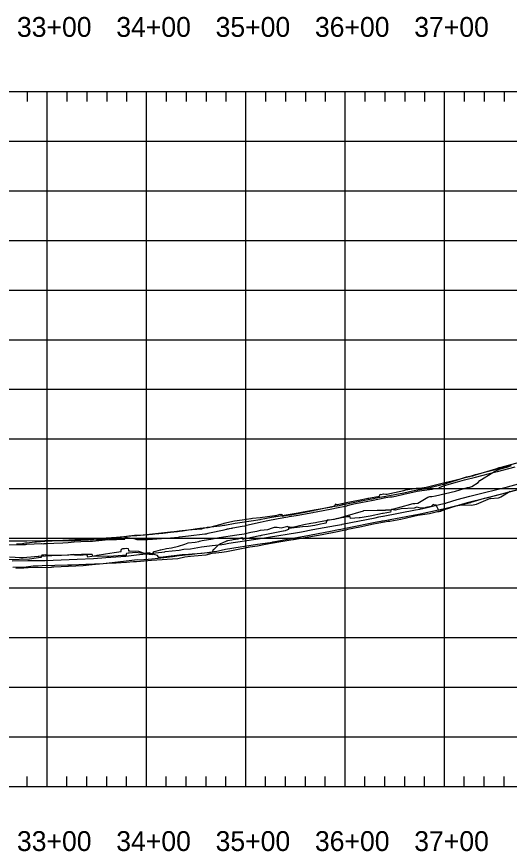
# Model space of a CAD drawing. Extents: x 704797 to 712284, y 374940 to 376945.
# Drawn here: x 710403 to 710899, y 375160 to 376001 of the extents above; entities that cross this region are included whole.
import ezdxf

# ---------------------------------------------------------------- set-up
doc = ezdxf.new("R2010")
doc.units = 0
for name, color, linetype in [('10', 7, 'Continuous'), ('12', 7, 'Continuous'), ('13', 7, 'Continuous'), ('61', 7, 'Continuous'), ('63', 7, 'Continuous'), ('Existing', 7, 'Continuous')]:
    doc.layers.add(name, color=color, linetype=linetype)

msp = doc.modelspace()

# ---------------------------------------------------------------- linework, layer by layer
at = {"layer": '10'}
for points in [[(710395.99, 375456.88), (710407.07, 375456.25), (710408.48, 375456.14), (710409.57, 375455.96), (710424.75, 375457.33), (710425, 375457.33), (710425.08, 375457.36), (710425.42, 375457.38), (710445.23, 375458.38), (710448.16, 375458.54), (710455.68, 375458.92), (710459.05, 375459), (710461.28, 375458.86), (710463.87, 375458.68), (710467.27, 375458.55), (710469.98, 375458.86), (710472.64, 375459.07), (710473.73, 375458.91), (710474.02, 375457.75), (710474.27, 375456.75), (710482.96, 375458.25), (710483.96, 375458.42), (710492.64, 375459.78), (710501.1, 375461.14), (710508.11, 375462.3), (710508.28, 375463.51), (710508.45, 375464.39), (710510, 375465.13), (710511.76, 375465.31), (710514.11, 375465.47), (710515.23, 375465.25), (710515.5, 375463.11), (710515.53, 375462.85), (710516.87, 375462.72), (710525.67, 375462.59), (710533.53, 375459.93), (710536.48, 375459.44), (710540.28, 375459.05), (710540.43, 375459.85), (710540.9, 375461.81), (710541.35, 375462.08), (710545.54, 375463.11), (710547.73, 375463.7), (710548.21, 375463.83), (710553.89, 375465.1), (710558.93, 375465.98), (710565.95, 375467.56), (710572.37, 375469.51), (710575.62, 375470.99), (710582.67, 375471.53), (710586.45, 375472.27), (710587.05, 375472.4), (710589.74, 375473.16), (710596.16, 375474.34), (710598.59, 375474.61), (710607.02, 375476.25), (710624.66, 375478.94), (710631.93, 375480.02), (710638.94, 375481.67), (710644.68, 375482.77), (710646.18, 375483.07), (710648.69, 375483.74), (710655.75, 375484.4), (710660.72, 375485.87), (710662.59, 375486.75), (710664.32, 375486.81), (710665.22, 375486.67), (710669.47, 375486.08), (710676.17, 375487.6), (710676.73, 375485.92), (710676.88, 375485.39), (710676.98, 375485.47), (710688.26, 375487.1), (710690.8, 375487.3), (710696.41, 375487.53), (710703.24, 375488.62), (710704.42, 375488.9), (710706.2, 375489.3), (710709.04, 375489.93), (710712.5, 375490.55), (710714.67, 375491.12), (710714.95, 375491.18), (710715.01, 375491.53), (710715.52, 375493.97), (710716.61, 375494.08), (710723.03, 375494.86), (710724.95, 375495.35), (710729.31, 375496.5), (710733.86, 375497.66), (710752.06, 375503.16), (710752.48, 375503.29), (710766.11, 375503.62), (710774.35, 375503.62), (710774.58, 375504.06), (710779.14, 375503.97), (710793.86, 375508), (710796.21, 375508.8), (710802.15, 375510.45), (710803.83, 375510.38), (710807.03, 375510.94), (710816.92, 375516.71), (710818.97, 375517.49), (710821.03, 375517.65), (710824.86, 375518.17), (710844.76, 375522.84), (710853.49, 375525.66), (710856.77, 375526.51), (710859.21, 375527.08), (710861.34, 375527.64), (710867.61, 375531.53), (710869.49, 375533.69), (710870.89, 375534.57), (710880.71, 375540.62), (710885.06, 375543.22), (710890.29, 375545.3), (710896.37, 375547.23), (710901.24, 375548.79)], [(710899.81, 375522.54), (710890.51, 375516.7), (710887.84, 375515.87), (710880, 375515.19), (710879.64, 375515.6), (710865.5, 375509.33), (710861.45, 375508.5), (710861.29, 375508.6), (710851.59, 375508.76), (710844.84, 375507.89), (710844.3, 375507.52), (710835.99, 375505.06), (710829.94, 375503.8), (710828.06, 375503.45), (710825.4, 375508.81), (710824.78, 375508.87), (710823.68, 375508.82), (710822.26, 375509.37), (710820.41, 375507.38), (710814.99, 375506.29), (710814.37, 375506.2), (710809.59, 375505.75), (710806.04, 375506.63), (710803.08, 375505.66), (710790.27, 375505.04), (710784.3, 375503.8), (710783.81, 375503.7), (710780.4, 375504.41), (710780.08, 375504.47), (710780.07, 375504.44), (710779.53, 375501.77), (710779.46, 375501.76), (710772, 375500.45), (710771.26, 375500.32), (710758.9, 375497.6), (710748.78, 375496), (710747.72, 375495.88), (710743.57, 375495.66), (710739.14, 375495.3), (710738.64, 375496.8), (710738.47, 375497.3), (710738.23, 375497.23), (710737.16, 375496.99), (710736.54, 375496.92), (710733.73, 375496.58), (710732.36, 375496.41), (710730.13, 375496), (710727.31, 375495.54), (710723.98, 375494.79), (710712.29, 375492.59), (710705.28, 375491.36), (710703.8, 375491.11), (710699.19, 375490.35), (710692.23, 375489.04), (710680.65, 375486.42), (710678.86, 375486.41), (710677.89, 375486.74), (710677.65, 375486.82), (710676.8, 375484.62), (710676.71, 375484.3), (710673.98, 375483.33), (710673.29, 375483.06), (710671.83, 375482.66), (710671.47, 375482.57), (710654.68, 375479.17), (710649.29, 375478.24), (710648.41, 375478.03), (710647.86, 375477.86), (710633.39, 375474.96), (710631.35, 375474.4), (710630.83, 375474.3), (710630.62, 375475.74), (710630.09, 375475.73), (710629.51, 375475.87), (710625.78, 375474.67), (710625.37, 375474.63), (710624.87, 375474.48), (710623.29, 375474.17), (710620.91, 375473.92), (710619.59, 375473.54), (710615.18, 375472.85), (710614.62, 375472.67), (710614.1, 375472.45), (710613.52, 375472.15), (710608.41, 375470.02), (710607.21, 375469.25), (710606.05, 375468.4), (710605.62, 375468.03), (710603.95, 375466.5), (710601.41, 375464.19), (710600.56, 375463.33), (710600.52, 375463.29), (710600.49, 375463.2), (710599.78, 375461.41), (710598.53, 375461.11), (710597.03, 375460.8), (710595.96, 375460.63), (710584.84, 375459.84), (710577.27, 375458.9), (710569.78, 375458.69), (710550.38, 375456.42), (710548.43, 375456.22), (710546.95, 375456.11), (710546.1, 375456.14), (710545.94, 375456.47), (710544.89, 375458.13), (710539.97, 375459.5), (710539.65, 375459.6), (710536.51, 375460.7), (710530.55, 375460.14), (710522.95, 375461.16), (710516.32, 375460.39), (710515.17, 375460.35), (710513.77, 375460.24), (710513.43, 375459.4), (710513.2, 375458.53), (710513.13, 375458.25), (710512.76, 375458.24), (710509.71, 375458.16), (710496.33, 375457.18), (710496.22, 375457.17), (710495.8, 375457.17), (710494.36, 375457.16), (710479.87, 375457.58), (710479.81, 375457.57), (710479.71, 375457.91), (710479.21, 375459.24), (710476.15, 375459.11), (710475.18, 375459.16), (710474.47, 375459.2), (710468.39, 375459.12), (710460.14, 375458.92), (710459.88, 375458.98), (710454.31, 375458.54), (710446, 375458.13), (710444.23, 375458.08), (710439.25, 375458.24), (710433.13, 375458.59), (710431.69, 375458.62), (710430.49, 375458.54), (710429.46, 375458.44), (710428.22, 375458.34), (710427.87, 375456.71), (710427.72, 375456.02), (710425.18, 375455.83), (710416.03, 375454.42), (710405.48, 375454.11), (710393.53, 375453.9)]]:
    msp.add_lwpolyline(points, dxfattribs=at)
at = {"layer": '12'}
for points in [[(710398.39, 375452.87), (710414.32, 375453.15), (710424.26, 375453.21), (710431.78, 375453.08), (710447.71, 375453.63), (710464.04, 375454.34), (710480.28, 375455), (710492.66, 375456.04), (710512.89, 375457.56), (710523.67, 375458.81), (710552.14, 375461.95), (710552.45, 375461.98), (710566.76, 375463.49), (710571.2, 375464.34), (710577.92, 375464.94), (710589.09, 375466.72), (710599.91, 375468.2), (710609.76, 375469.13), (710611.91, 375469.45), (710616.6, 375470.37), (710650.7, 375475.42), (710652.7, 375475.77), (710656.46, 375476.47), (710685.67, 375481.36), (710685.83, 375481.38), (710689.76, 375482.08), (710701.21, 375484.13), (710724.08, 375488.24), (710728.13, 375489.02), (710730.14, 375489.43), (710730.26, 375489.49), (710730.77, 375489.66), (710763.88, 375496.16), (710767.71, 375496.94), (710771.7, 375497.73), (710772.13, 375497.71), (710804.48, 375503.94), (710808.82, 375504.91), (710811.85, 375505.35), (710834.36, 375510.7), (710834.68, 375510.72), (710834.98, 375510.77), (710835.69, 375511.11), (710846.59, 375514.59), (710859.19, 375517.78), (710860.69, 375518.16), (710861.91, 375518.48), (710897.08, 375527.35), (710908.36, 375530.43)], [(710399.3, 375446.46), (710412.7, 375446.66), (710414.93, 375447.06), (710419.55, 375447.54), (710424.85, 375447.68), (710428.62, 375447.9), (710454.23, 375448.78), (710456.62, 375448.83), (710456.95, 375448.82), (710457.25, 375448.81), (710457.52, 375448.79), (710457.77, 375448.78), (710458, 375448.78), (710458.41, 375448.78), (710472.79, 375449.34), (710490.21, 375450), (710493.11, 375450.34), (710504.96, 375451.81), (710519.13, 375453.43), (710524.2, 375453.98), (710526.58, 375453.84), (710535.58, 375454.58), (710542.35, 375455.22), (710559.91, 375457.18), (710568.98, 375458.29), (710569.53, 375458.41), (710570.14, 375458.52), (710570.85, 375458.62), (710571.66, 375458.73), (710572.59, 375458.85), (710576.09, 375459.29), (710579.57, 375459.71), (710589.31, 375460.47), (710599.86, 375461.91), (710601.6, 375462.08), (710603.18, 375462.28), (710613.36, 375464.59), (710627.92, 375466.96), (710645.34, 375469.69), (710658.16, 375471.06), (710659.3, 375471.19), (710660.42, 375471.45), (710660.94, 375471.8), (710661.12, 375471.96), (710679.51, 375475.13), (710692.55, 375477.59), (710718.91, 375482.47), (710727.13, 375484.2), (710727.73, 375484.28), (710735.9, 375485.98), (710765.66, 375491.93), (710769.65, 375492.64), (710770.08, 375492.7), (710770.9, 375492.86), (710772.11, 375493.09), (710802.36, 375498.88), (710809.32, 375500), (710827.62, 375504), (710836.75, 375506), (710843.45, 375507.63), (710860.33, 375511.62), (710860.46, 375511.8), (710874.16, 375515.74), (710893.69, 375520.74), (710915.47, 375526.74)]]:
    msp.add_lwpolyline(points, dxfattribs=at)
at = {"layer": '13'}
msp.add_lwpolyline([(710913.53, 375525.73), (710892.38, 375520.16), (710875.62, 375515.81), (710856.57, 375511.01), (710845.34, 375507.82), (710833.51, 375504.05), (710829.91, 375502.33), (710828.36, 375502.04), (710826.76, 375501.96), (710818.77, 375500.06), (710806.94, 375498.35), (710789.86, 375494.53), (710778.69, 375492.38), (710778.22, 375492.4), (710777.1, 375492.44), (710762.37, 375489.54), (710748.54, 375486.76), (710736.28, 375484.38), (710734.3, 375483.72), (710733.84, 375483.52), (710726.07, 375481.93), (710710.78, 375479.06), (710697.34, 375476.67), (710681.77, 375473.95), (710681.17, 375473.88), (710669.08, 375471.88), (710653.66, 375469.02), (710645.59, 375467.64), (710637.88, 375466.51), (710614.24, 375461.95), (710609.74, 375461.28), (710603.63, 375460.36), (710599.6, 375459.97), (710593.44, 375458.36), (710578.12, 375457.17), (710572.43, 375456.48), (710565.29, 375454.85), (710538.67, 375453.13), (710527.76, 375451.96), (710523.85, 375451.82), (710520.64, 375451.67), (710513.74, 375451.08), (710503.08, 375450.3), (710494.32, 375450.11), (710482.34, 375448.97), (710479.11, 375448.63), (710478.8, 375448.65), (710469.92, 375447.83), (710469.84, 375447.82), (710440.42, 375446.32), (710438.61, 375446.21), (710437.63, 375446.16), (710437.37, 375446.18), (710414.5, 375445.57), (710410.29, 375445.46), (710407.23, 375445.28), (710402.16, 375445.16)], dxfattribs=at)
at = {"layer": '61'}
for p, q in [((708133.69, 375925.47), (712133.69, 375925.47)), ((710413.69, 375925.47), (710413.69, 375915.47)), ((710433.69, 375225.47), (710433.69, 375925.47)), ((710453.69, 375925.47), (710453.69, 375915.47)), ((710473.69, 375925.47), (710473.69, 375915.47)), ((710493.69, 375925.47), (710493.69, 375915.47)), ((710513.69, 375925.47), (710513.69, 375915.47)), ((710533.69, 375225.47), (710533.69, 375925.47)), ((710553.69, 375925.47), (710553.69, 375915.47)), ((710573.69, 375925.47), (710573.69, 375915.47)), ((710593.69, 375925.47), (710593.69, 375915.47)), ((710613.69, 375925.47), (710613.69, 375915.47)), ((710633.69, 375225.47), (710633.69, 375925.47)), ((710653.69, 375925.47), (710653.69, 375915.47)), ((710673.69, 375925.47), (710673.69, 375915.47)), ((710693.69, 375925.47), (710693.69, 375915.47)), ((710713.69, 375925.47), (710713.69, 375915.47)), ((710733.69, 375225.47), (710733.69, 375925.47)), ((710753.69, 375925.47), (710753.69, 375915.47)), ((710773.69, 375925.47), (710773.69, 375915.47)), ((710793.69, 375925.47), (710793.69, 375915.47)), ((710813.69, 375925.47), (710813.69, 375915.47)), ((710833.69, 375225.47), (710833.69, 375925.47)), ((710853.69, 375925.47), (710853.69, 375915.47)), ((710873.69, 375925.47), (710873.69, 375915.47)), ((710893.69, 375925.47), (710893.69, 375915.47)), ((708133.69, 375875.47), (712133.69, 375875.47)), ((708133.69, 375825.47), (712133.69, 375825.47)), ((708133.69, 375775.47), (712133.69, 375775.47)), ((708133.69, 375725.47), (712133.69, 375725.47)), ((708133.69, 375675.47), (712133.69, 375675.47)), ((708133.69, 375625.47), (712133.69, 375625.47)), ((708133.69, 375575.47), (712133.69, 375575.47)), ((708133.69, 375525.47), (712133.69, 375525.47)), ((708133.69, 375475.47), (712133.69, 375475.47)), ((708133.69, 375425.47), (712133.69, 375425.47)), ((708133.69, 375375.47), (712133.69, 375375.47)), ((708133.69, 375325.47), (712133.69, 375325.47)), ((708133.69, 375275.47), (712133.69, 375275.47)), ((710413.69, 375225.47), (710413.69, 375235.47)), ((710453.69, 375225.47), (710453.69, 375235.47)), ((710473.69, 375225.47), (710473.69, 375235.47)), ((710493.69, 375225.47), (710493.69, 375235.47)), ((710513.69, 375225.47), (710513.69, 375235.47)), ((710553.69, 375225.47), (710553.69, 375235.47)), ((710573.69, 375225.47), (710573.69, 375235.47)), ((710593.69, 375225.47), (710593.69, 375235.47)), ((710613.69, 375225.47), (710613.69, 375235.47)), ((710653.69, 375225.47), (710653.69, 375235.47)), ((710673.69, 375225.47), (710673.69, 375235.47)), ((710693.69, 375225.47), (710693.69, 375235.47)), ((710713.69, 375225.47), (710713.69, 375235.47)), ((710753.69, 375225.47), (710753.69, 375235.47)), ((710773.69, 375225.47), (710773.69, 375235.47)), ((710793.69, 375225.47), (710793.69, 375235.47)), ((710813.69, 375225.47), (710813.69, 375235.47)), ((710853.69, 375225.47), (710853.69, 375235.47)), ((710873.69, 375225.47), (710873.69, 375235.47)), ((710893.69, 375225.47), (710893.69, 375235.47)), ((708133.69, 375225.47), (712133.69, 375225.47))]:
    msp.add_line(p, q, dxfattribs=at)
at = {"layer": '63'}
for points in [[(710402.77, 375469.93), (710407.34, 375470.02), (710411.98, 375470.88), (710413.33, 375471.02), (710421.36, 375471.87), (710422.96, 375471.92), (710431.4, 375472.42), (710438.76, 375472.85), (710446.17, 375473.12), (710449.47, 375473.19), (710455.02, 375473.3), (710456.21, 375473.29), (710457.27, 375473.24), (710458.22, 375473.18), (710459.06, 375473.15), (710459.87, 375473.16), (710461.29, 375473.17), (710467.54, 375473.44), (710483.44, 375474.12), (710485.6, 375474.29), (710490.63, 375474.7), (710494.69, 375475.18), (710503.67, 375476.32), (710513.65, 375477.59), (710516.12, 375477.94), (710521.74, 375478.56), (710523.53, 375478.75), (710527.76, 375478.51), (710539.81, 375479.57), (710542.15, 375479.77), (710550.13, 375480.58), (710557.87, 375481.47), (710564.9, 375482.28), (710565.91, 375482.49), (710567.06, 375482.69), (710568.41, 375482.89), (710570.01, 375483.09), (710571.87, 375483.32), (710575.94, 375483.81), (710579.33, 375484.22), (710579.7, 375484.26), (710589.31, 375484.96), (710591.27, 375485.63), (710594.01, 375486.33), (710594.27, 375486.4), (710595.91, 375486.33), (710597.46, 375486.63), (710598.98, 375487.07), (710611.4, 375490.5), (710612.07, 375490.68), (710614.51, 375491.31), (710622.41, 375492.87), (710630.14, 375494.04), (710638.87, 375495.37), (710639.08, 375495.42), (710640.45, 375495.55), (710648.21, 375496.47), (710662.96, 375498.24), (710664.04, 375498.49), (710666.28, 375499.14), (710668.25, 375499.71), (710668.49, 375499.34), (710669.4, 375499.58), (710669.68, 375499.54), (710669.88, 375499.58), (710669.9, 375499.53), (710670.46, 375497.55), (710670.82, 375497.87), (710673.72, 375498.27), (710684.34, 375500.24), (710699.71, 375503.08), (710701, 375503.32), (710701.17, 375503.36), (710701.66, 375503.48), (710702.06, 375503.57), (710702.41, 375503.65), (710702.63, 375503.7), (710704.74, 375504.16), (710720.48, 375507.5), (710722.44, 375507.91), (710722.83, 375507.97), (710723.33, 375508.03), (710724.02, 375509.54), (710724.19, 375509.93), (710724.65, 375510), (710725.12, 375509.61), (710726.06, 375509.55), (710736.31, 375511.75), (710738.55, 375512.19), (710750.42, 375514.49), (710756.61, 375515.73), (710757.58, 375515.93), (710759.24, 375516.28), (710768.18, 375517.88), (710768.4, 375518.08), (710768.45, 375518.1), (710768.95, 375519.71), (710769.15, 375519.96), (710769.99, 375519.53), (710772.25, 375520.05), (710774.68, 375520), (710776.06, 375519.97), (710778.65, 375520.67), (710792.75, 375523.68), (710795.01, 375524.16), (710805.29, 375525.89), (710808.06, 375525.77), (710810.82, 375526.25), (710815.21, 375527.02), (710819.41, 375527.91), (710828.88, 375530.36), (710834.02, 375531.68), (710841.4, 375533.43), (710846.95, 375534.75), (710858.72, 375537.55), (710859.69, 375537.82), (710860.01, 375537.99), (710862.15, 375538.5), (710865.02, 375539.34), (710885.34, 375545.26), (710888.7, 375546.63), (710889.2, 375546.79), (710890.74, 375547.15), (710924.02, 375556.13)], [(710395.27, 375468.69), (710406.5, 375469.02), (710409.17, 375469.07), (710409.68, 375469.09), (710410.25, 375469.17), (710411.98, 375469.31), (710413.33, 375469.38), (710428.03, 375470.13), (710428.37, 375470.04), (710430.48, 375469.92), (710430.49, 375470.33), (710431.4, 375470.33), (710431.68, 375470.33), (710433.92, 375470.1), (710440.52, 375470.43), (710449.47, 375470.9), (710454.85, 375471.19), (710460.93, 375471.87), (710467.54, 375472.13), (710476.9, 375472.6), (710477.84, 375472.58), (710477.88, 375472.55), (710479.26, 375472.49), (710485.6, 375473.12), (710495.39, 375474.1), (710495.49, 375474.11), (710499.96, 375474.19), (710503.67, 375474.3), (710511.81, 375474.56), (710511.88, 375474.55), (710511.97, 375474.56), (710512.02, 375476.26), (710514.66, 375476.07), (710521.09, 375475.3), (710521.74, 375475.1), (710523.15, 375474.69), (710523.92, 375474.35), (710525.47, 375474.3), (710526.27, 375474.22), (710534.61, 375474.15), (710539.81, 375474.58), (710557.87, 375476.03), (710565.67, 375476.65), (710566.34, 375476.68), (710566.48, 375476.69), (710566.5, 375476.7), (710566.96, 375476.76), (710575.94, 375477.83), (710592.65, 375479.81), (710594.01, 375480.04), (710594.97, 375480.2), (710595.89, 375480.46), (710597.17, 375480.8), (710612.07, 375484.09), (710614.13, 375484.54), (710614.6, 375484.69), (710615.29, 375484.88), (710616.23, 375485.1), (710617.43, 375485.36), (710618.98, 375485.67), (710619.85, 375485.77), (710620.71, 375485.93), (710630.14, 375487.65), (710632.69, 375488.11), (710633.99, 375488.44), (710634.46, 375488.61), (710648.21, 375491.77), (710651.25, 375492.46), (710654.23, 375492.98), (710666.28, 375495.26), (710676.04, 375497.1), (710678.76, 375497.56), (710679.6, 375497.66), (710684.34, 375498.5), (710701.11, 375501.47), (710702.41, 375501.7), (710704.49, 375502.08), (710720.48, 375505.12), (710725.16, 375506.01), (710735.43, 375508.13), (710736.02, 375508.4), (710738.55, 375509.24), (710738.61, 375509.27), (710742.39, 375510), (710756.61, 375512.88), (710760.34, 375513.64), (710774.68, 375516.47), (710779.04, 375517.33), (710781.03, 375517.26), (710784.58, 375517.94), (710792.75, 375519.76), (710806.24, 375522.77), (710810.82, 375523.42), (710821.43, 375524.95), (710823.81, 375525.51), (710825.9, 375525.61), (710827.93, 375525.99), (710828.88, 375526.44), (710832.65, 375528.24), (710835.98, 375529.29), (710846.95, 375532.4), (710853.88, 375534.35), (710865.02, 375537.13), (710885.49, 375542.23), (710886.99, 375542.62), (710905.05, 375547.33)]]:
    msp.add_lwpolyline(points, dxfattribs=at)
at = {"layer": 'Existing'}
msp.add_lwpolyline([(710395.27, 375472.86), (710404.92, 375472.97), (710405.53, 375472.97), (710413.33, 375473), (710431.4, 375473.08), (710436.93, 375473.1), (710438.69, 375473.14), (710440.5, 375473.23), (710449.47, 375473.64), (710467.54, 375474.46), (710470.35, 375474.59), (710470.56, 375474.6), (710485.6, 375475.41), (710488.7, 375475.57), (710493.28, 375475.99), (710495.58, 375476.03), (710498.53, 375476.24), (710503.67, 375476.65), (710521.74, 375478.1), (710522.51, 375478.16), (710524.09, 375478.23), (710539.81, 375479.98), (710557.87, 375481.99), (710558.87, 375482.1), (710564.3, 375482.48), (710566.48, 375482.99), (710575.94, 375483.87), (710576.08, 375483.89), (710587.51, 375485.74), (710593.73, 375486.26), (710594.01, 375486.33), (710595.23, 375486.66), (710607.76, 375487.89), (710612.07, 375488.56), (710612.65, 375488.65), (710622.96, 375490.71), (710630.14, 375491.79), (710648.21, 375494.52), (710649.36, 375494.69), (710652.95, 375495.32), (710659.58, 375496.57), (710666.28, 375497.71), (710684.34, 375500.76), (710684.69, 375500.82), (710684.94, 375500.85), (710691.35, 375501.99), (710702.41, 375503.99), (710720.48, 375507.24), (710721.49, 375507.43), (710727.73, 375508.61), (710730.84, 375509.26), (710731.02, 375509.34), (710731.8, 375509.6), (710738.55, 375510.93), (710756.61, 375514.47), (710761.03, 375515.34), (710766.73, 375516.5), (710772.68, 375517.67), (710773.31, 375517.65), (710774.68, 375517.91), (710792.75, 375521.38), (710801.71, 375523.1), (710808.46, 375524.61), (710810.82, 375524.95), (710813.2, 375525.29), (710828.88, 375529), (710832.81, 375529.93), (710833.38, 375529.96), (710833.94, 375530.06), (710835.24, 375530.68), (710846.95, 375534.41), (710855.89, 375537.25), (710860.81, 375538.5), (710865.02, 375539.6), (710891.16, 375546.43), (710899.8, 375548.64)], dxfattribs=at)

# ---------------------------------------------------------------- texts
at = {"layer": '61'}
for s, p in [('33+00', (710403.32, 375980.47)), ('34+00', (710503.32, 375980.47)), ('35+00', (710603.32, 375980.47)), ('36+00', (710703.32, 375980.47)), ('37+00', (710803.32, 375980.47)), ('33+00', (710403.32, 375160.47)), ('34+00', (710503.32, 375160.47)), ('35+00', (710603.32, 375160.47)), ('36+00', (710703.32, 375160.47)), ('37+00', (710803.32, 375160.47))]:
    msp.add_text(s, height=20, dxfattribs=at).set_placement(p)

doc.saveas('drawing.dxf')
